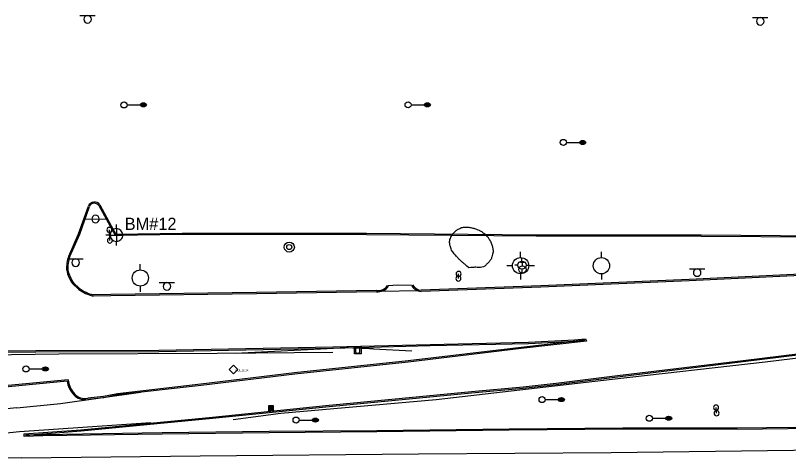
# Model space of a CAD drawing. Extents: x 2145380 to 2156929, y 139568 to 149130.
# Drawn here: x 2146530.1 to 2146909.9, y 143094.5 to 143313.3 of the extents above; entities that cross this region are included whole.
import ezdxf

# ---------------------------------------------------------------- set-up
doc = ezdxf.new("R2010")
doc.units = 0
for name, color, linetype in [('Default', 7, 'Continuous'), ('SURV_Benchmark', 7, 'Continuous'), ('SURV_Text', 7, 'Continuous'), ('TOPO_Asphalt', 7, 'Continuous'), ('TOPO_Curb Back', 7, 'Continuous'), ('TOPO_Guardrail', 7, 'Continuous'), ('TOPO_Light Pole', 7, 'Continuous'), ('TOPO_Misc', 7, 'Continuous'), ('TOPO_Power Pole', 7, 'Continuous'), ('TOPO_Power Pullbox', 7, 'Continuous'), ('TOPO_San Manhole', 7, 'Continuous'), ('TOPO_Sign', 7, 'Continuous'), ('TOPO_Tree Line', 7, 'Continuous'), ('TOPO_Water Fire Hydrant', 7, 'Continuous'), ('TOPO_Water Valve', 7, 'Continuous')]:
    doc.layers.add(name, color=color, linetype=linetype)

# ---------------------------------------------------------------- blocks, each defined once
blk = doc.blocks.new('LP')
at = {"layer": 'TOPO_Light Pole'}
blk.add_line((3.81, 0), (20.32, 0), dxfattribs=at)
for points in [[(20.32, 0), (27.94, 0)], [(20.32, 0), (23.5, 0)], [(20.83, 1.27), (27.43, 1.27)], [(20.83, 1.27), (23.5, 1.27)], [(23.71, 1.27), (27.43, 1.27)], [(23.71, 0), (27.94, 0)], [(20.83, -1.27), (27.43, -1.27)], [(20.83, -1.27), (23.5, -1.27)], [(23.71, -1.27), (27.43, -1.27)]]:
    blk.add_lwpolyline(points, dxfattribs=at)
blk.add_circle((0, 0), 3.81, dxfattribs=at)
blk.add_ellipse((24.13, 0), major_axis=(3.81, 0), ratio=0.666667, dxfattribs=at)
blk = doc.blocks.new('POST')
at = {"layer": 'TOPO_Misc'}
for start, end in [(89.99996, 180.00004), (179.99996, 270.00004), (359.99996, 90.00004), (269.99996, 0.00004)]:
    blk.add_arc((-0.01, 0.03), 3.16, start, end, dxfattribs=at)
blk = doc.blocks.new('FIRHYD')
at = {"layer": 'TOPO_Water Fire Hydrant'}
for p, q in [((-0.02, 10.16), (-0.03, 17.34)), ((10.16, 0.02), (17.34, 0.03)), ((-10.16, -0.02), (-17.34, -0.03)), ((0.02, -10.16), (0.03, -17.34))]:
    blk.add_line(p, q, dxfattribs=at)
blk.add_circle((0, 0), 10.16, dxfattribs=at)
blk = doc.blocks.new('CB')
at = {"layer": 'TOPO_Misc'}
for p, q in [((-3.08, 2.99), (3.24, 2.99)), ((-3.08, 2.68), (3.24, 2.68)), ((-3.08, 2.36), (3.24, 2.36)), ((-3.08, 2.05), (3.24, 2.05)), ((-3.08, 1.73), (3.24, 1.73)), ((-3.08, 1.4), (3.24, 1.4)), ((-3.08, 1.1), (3.24, 1.1)), ((-3.08, 0.77), (3.24, 0.77)), ((-3.08, 0.46), (3.24, 0.46)), ((-3.08, 0.14), (3.24, 0.14)), ((-3.08, -0.17), (3.24, -0.17)), ((-3.08, -0.48), (3.24, -0.48)), ((-3.08, -0.8), (3.24, -0.8)), ((-3.08, -1.11), (3.26, -1.11)), ((-3.08, -1.43), (3.26, -1.43)), ((-3.08, -1.75), (3.26, -1.75)), ((-3.08, -2.07), (3.26, -2.07)), ((-3.08, -2.39), (3.26, -2.39)), ((-3.08, -2.7), (3.26, -2.7)), ((-3.08, -3.02), (3.26, -3.02))]:
    blk.add_line(p, q, dxfattribs=at)
blk.add_lwpolyline([(3.26, -3.29), (3.24, 3.05), (-3.09, 3.04), (-3.08, -3.3), (3.26, -3.29)], dxfattribs=at)
blk = doc.blocks.new('POWPOL')
at = {"layer": 'TOPO_Power Pole'}
for p, q in [((0, 10.16), (0, 17.34)), ((0, -10.16), (0, -17.34))]:
    blk.add_line(p, q, dxfattribs=at)
blk.add_circle((0, 0), 10.16, dxfattribs=at)
blk = doc.blocks.new('pulbox')
at = {"layer": 'Default'}
blk.add_lwpolyline([(-5.38, -0.01), (-0.02, 5.42), (5.4, 0.06), (0.05, -5.36), (-5.38, -0.01)], dxfattribs=at)
blk.add_text('PULLBOX', height=2.54, dxfattribs=at).set_placement((2.54, -2.54))
blk = doc.blocks.new('WATVAL')
at = {"layer": 'Default'}
for p, q in [((-2.25, 9), (2.25, 9)), ((0, 4.5), (0, 9))]:
    blk.add_line(p, q, dxfattribs=at)
blk.add_circle((0, 0), 4.5, dxfattribs=at)
blk = doc.blocks.new('EXMHSS')
at = {"layer": 'Default'}
for radius in [6.3, 3.13]:
    blk.add_circle((0, 0), radius, dxfattribs=at)
blk = doc.blocks.new('BM')
at = {"layer": 'SURV_Benchmark'}
for p, q in [((0, 2.49), (0, 4.15)), ((-2.49, 0), (-4.16, 0)), ((4.16, 0), (2.49, 0)), ((0, -4.16), (0, -2.49))]:
    blk.add_line(p, q, dxfattribs=at)
for points in [[(-2.5, 0), (-2.49, 0), (0, 0), (0, -2.49), (0, -2.49)], [(-2.5, 0), (-2.49, 0), (0, 0), (0, -2.49), (0, -2.49)], [(0, 2.49), (0, 2.49), (0, 0), (2.49, 0), (2.49, 0), (2.49, 0)], [(0, 2.49), (0, 2.49), (0, 0), (2.49, 0), (2.49, 0), (2.49, 0), (2.49, 0)]]:
    blk.add_lwpolyline(points, dxfattribs=at)
for start, end in [(90.0638, 180.0068), (0.0638, 90.0068), (0.0638, 90.0068), (180.0638, 270.0068), (180.0638, 270.0068), (269.9472, 359.9927)]:
    blk.add_arc((0, 0), 2.5, start, end, dxfattribs=at)

msp = doc.modelspace()

# ---------------------------------------------------------------- linework, layer by layer
at = {"layer": 'TOPO_Asphalt'}
for p, q in [((2146576.46, 143202.65), (2146576.24, 143207.86)), ((2146727.7, 143177.96), (2146709.51, 143177.61))]:
    msp.add_line(p, q, dxfattribs=at)
for points in [[(2146712.97, 143180.61), (2146717.98, 143180.83), (2146724.61, 143180.64)], [(2146530.81, 143120.35), (2146552.18, 143122.58), (2146591.58, 143128.04)], [(2146530.81, 143120.35), (2146454.22, 143112.88)], [(2146596.66, 143112.95), (2146532, 143108.56), (2146508.54, 143106.19)], [(2146533.08, 143095.79), (2146446.58, 143095), (2146359.8, 143094.46), (2146423.36, 143099.13), (2146508.54, 143106.19)], [(2146533.08, 143095.79), (2146620.8, 143096.7), (2146728.01, 143097.79), (2146822.76, 143098.41), (2146912.25, 143099.54), (2147020.54, 143100.24), (2147131.17, 143101.32), (2147235.2, 143102.32), (2147277.67, 143102.76)]]:
    msp.add_lwpolyline(points, dxfattribs=at)
at = {"layer": 'TOPO_Curb Back'}
for points in [[(2146556.23, 143194.94), (2146561.06, 143205.93), (2146565.9, 143219.62)], [(2146556.79, 143194.71), (2146561.62, 143205.7), (2146566.46, 143219.39)], [(2146571.05, 143219.87), (2146576.58, 143209.64), (2146578.98, 143205.21), (2146612.05, 143205.72), (2146702.61, 143205.68), (2146785.83, 143204.89), (2146866.96, 143204.87), (2146925.47, 143204.4), (2146939.15, 143204.34), (2146943.78, 143207.95), (2146941.54, 143212.17)], [(2146571.55, 143220.19), (2146577.11, 143209.93), (2146579.34, 143205.82), (2146612.05, 143206.32), (2146702.61, 143206.28), (2146785.83, 143205.49), (2146866.96, 143205.47), (2146925.48, 143205), (2146938.94, 143204.94), (2146943.01, 143208.11), (2146941.09, 143211.74)], [(2146936.56, 143186.42), (2146861.15, 143182.86), (2146788.22, 143179.79), (2146729.35, 143177.64)], [(2146936.54, 143187.02), (2146861.12, 143183.46), (2146788.2, 143180.39), (2146729.36, 143178.24)], [(2146561.15, 143178.6), (2146558.1, 143181.44)], [(2146561.53, 143179.06), (2146558.56, 143181.83)], [(2146707.46, 143177.43), (2146648.5, 143176.48), (2146576.92, 143175.53), (2146568.17, 143175.36)], [(2146707.48, 143178.03), (2146648.49, 143177.08), (2146576.91, 143176.13), (2146568.24, 143175.96)], [(2145888.42, 143132.54), (2145934.97, 143136.29), (2145983.97, 143139.68), (2146045.76, 143137.81), (2146115.67, 143142.08), (2146170.97, 143145.46), (2146234.1, 143146.24), (2146328.36, 143147.21), (2146412.4, 143147.87), (2146464.49, 143148.31), (2146540.06, 143148.59), (2146600.53, 143148.76), (2146685.95, 143150.38), (2146733.76, 143151.59), (2146782.06, 143152.69), (2146804.67, 143153.83), (2146810.22, 143154.32), (2146810.59, 143153.13), (2146778.61, 143149.5), (2146723.01, 143142.86), (2146667.3, 143136.97), (2146621.29, 143131.42), (2146580.25, 143126.75), (2146573.42, 143125.34)], [(2145888.46, 143131.94), (2145935.02, 143135.69), (2145983.98, 143139.08), (2146045.76, 143137.21), (2146115.7, 143141.48), (2146170.99, 143144.86), (2146234.11, 143145.64), (2146328.36, 143146.61), (2146412.4, 143147.27), (2146464.49, 143147.71), (2146540.06, 143147.99), (2146600.54, 143148.16), (2146685.97, 143149.78), (2146733.77, 143150.99), (2146782.08, 143152.09), (2146804.71, 143153.23), (2146809.79, 143153.68), (2146809.8, 143153.64), (2146778.54, 143150.09), (2146722.94, 143143.46), (2146667.23, 143137.57), (2146621.22, 143132.02), (2146580.15, 143127.34), (2146573.3, 143125.93)], [(2146971.16, 143110.85), (2146884.74, 143109.79), (2146828.41, 143109.86), (2146772.57, 143109.36), (2146707.64, 143108.53), (2146654.7, 143108.12), (2146602.15, 143107.42), (2146543.46, 143106.54), (2146534.41, 143106.32), (2146534.33, 143107.54), (2146562.24, 143109.64), (2146626.86, 143115.86), (2146682.49, 143121.45), (2146754.14, 143128.38), (2146779.5, 143130.73), (2146795.72, 143132.53), (2146825.79, 143136.29), (2146887.61, 143143.7), (2146962.26, 143152.91)], [(2146971.15, 143111.44), (2146884.73, 143110.39), (2146828.41, 143110.46), (2146772.57, 143109.96), (2146707.63, 143109.13), (2146654.7, 143108.72), (2146602.14, 143108.02), (2146543.45, 143107.14), (2146534.97, 143106.93), (2146534.96, 143106.98), (2146562.29, 143109.04), (2146626.92, 143115.26), (2146682.55, 143120.86), (2146754.2, 143127.78), (2146779.56, 143130.13), (2146795.79, 143131.93), (2146825.86, 143135.69), (2146887.68, 143143.1), (2146962.33, 143152.31)], [(2146555.92, 143134.2), (2146526.51, 143131.33), (2146455.1, 143123.91), (2146431.26, 143121.71), (2146396.27, 143119.46), (2146350.09, 143117.2), (2146299.91, 143116.09), (2146246.29, 143114.58), (2146189.97, 143112.89), (2146131.43, 143111.03)], [(2146555.41, 143133.54), (2146526.57, 143130.74), (2146455.16, 143123.32), (2146431.31, 143121.11), (2146396.31, 143118.86), (2146350.11, 143116.6), (2146299.92, 143115.49), (2146246.31, 143113.98), (2146189.99, 143112.29), (2146131.45, 143110.43)], [(2146573.32, 143125.94), (2146565.55, 143125.11)], [(2146573.39, 143125.34), (2146565.64, 143124.52)]]:
    msp.add_lwpolyline(points, dxfattribs=at)
for centre, radius, start, end in [((2146568.89, 143218.27), 3.28, 35.8736, 155.7101), ((2146568.89, 143218.27), 2.68, 36.6665, 155.1999), ((2146571.29, 143189.22), 16.1, 159.2169, 184.0265), ((2146571.29, 143189.22), 15.5, 159.2728, 183.8644), ((2146573.83, 143192.18), 19.04, 192.4019, 214.3313), ((2146573.83, 143192.18), 18.44, 192.5386, 214.1261), ((2146572.65, 143194.28), 19.45, 233.753, 256.6902), ((2146572.65, 143194.28), 18.85, 233.8598, 256.4606), ((2146707.92, 143184.13), 6.71, 266.1076, 324.0825), ((2146707.92, 143184.13), 6.11, 265.8766, 324.0825), ((2146729.6, 143183.28), 5.65, 207.8693, 267.5079), ((2146729.6, 143183.28), 5.05, 207.8693, 267.2427), ((2146568.01, 143135.54), 12.76, 188.9783, 222.7059), ((2146568.01, 143135.54), 12.16, 186.3185, 222.7266), ((2146564.23, 143131.89), 7.51, 221.877, 280.814), ((2146564.23, 143131.89), 6.91, 221.8413, 281.0158)]:
    msp.add_arc(centre, radius, start, end, dxfattribs=at)
at = {"layer": 'TOPO_Guardrail'}
for points in [[(2147049.65, 143160.58), (2146984.46, 143153.27), (2146898.4, 143142.89), (2146823.2, 143134.27), (2146736.79, 143124.36), (2146660.39, 143117.58), (2146637.08, 143114.45)], [(2146551.37, 143146.86), (2146629.12, 143147.21), (2146686.04, 143147.75)], [(2146637.99, 143147.3), (2146689.63, 143149.87)], [(2146706.03, 143149.31), (2146724.88, 143148.43)], [(2146448.48, 143146.27), (2146516.32, 143146.42), (2146551.37, 143146.86)]]:
    msp.add_lwpolyline(points, dxfattribs=at)
msp.add_arc((2146685.9, 142804.41), 345.49, 86.6594, 89.3802, dxfattribs=at)
at = {"layer": 'TOPO_Misc'}
for p, q in [((2146697.21, 143150.16), (2146697.21, 143147.76)), ((2146699.29, 143147.76), (2146699.29, 143150.17))]:
    msp.add_line(p, q, dxfattribs=at)
msp.add_lwpolyline([(2146696.62, 143146.85), (2146696.62, 143150.61), (2146699.88, 143150.61), (2146699.88, 143146.85), (2146696.62, 143146.85)], dxfattribs=at)
msp.add_arc((2146698.25, 143148.58), 1.32, 218.3412, 322.0625, dxfattribs=at)
at = {"layer": 'TOPO_Sign'}
for points in [[(2146561.76, 143313.31), (2146569.26, 143313.32)], [(2146563.65, 143311.45), (2146563.65, 143311.45)], [(2146565.51, 143313.31), (2146565.51, 143313.31)], [(2146567.38, 143311.45), (2146567.38, 143311.45)], [(2146892.26, 143312.33), (2146899.75, 143312.34)], [(2146894.14, 143310.46), (2146894.14, 143310.46)], [(2146896.01, 143312.33), (2146896.01, 143312.33)], [(2146897.88, 143310.46), (2146897.88, 143310.46)], [(2146565.51, 143309.58), (2146565.51, 143309.58)], [(2146896.01, 143308.6), (2146896.01, 143308.6)], [(2146564.27, 143213.21), (2146575.15, 143213.27)], [(2146555.89, 143193.69), (2146563.38, 143193.7)], [(2146559.64, 143193.69), (2146559.64, 143193.69)], [(2146557.77, 143191.82), (2146557.77, 143191.82)], [(2146559.64, 143189.95), (2146559.64, 143189.95)], [(2146561.51, 143191.82), (2146561.51, 143191.82)], [(2146747.71, 143183.96), (2146747.78, 143186.22)], [(2146861.25, 143188.78), (2146868.74, 143188.78)], [(2146863.13, 143186.91), (2146863.13, 143186.91)], [(2146865, 143188.78), (2146865, 143188.78)], [(2146865, 143185.04), (2146865, 143185.04)], [(2146866.86, 143186.91), (2146866.86, 143186.91)], [(2146600.71, 143181.98), (2146608.2, 143181.99)], [(2146604.46, 143181.98), (2146604.46, 143181.98)], [(2146602.59, 143180.11), (2146602.59, 143180.11)], [(2146604.46, 143178.24), (2146604.46, 143178.24)], [(2146606.32, 143180.11), (2146606.32, 143180.11)], [(2146874.53, 143117.68), (2146874.31, 143120.48)]]:
    msp.add_lwpolyline(points, dxfattribs=at)
for centre, radius, start, end in [((2146565.51, 143311.45), 1.87, 90, 180), ((2146565.51, 143311.45), 1.87, 180, 270), ((2146565.51, 143311.45), 1.87, 360, 90), ((2146565.51, 143311.45), 1.87, 270, 0), ((2146896.01, 143310.46), 1.87, 90, 180), ((2146896.01, 143310.46), 1.87, 180, 270), ((2146896.01, 143310.46), 1.87, 360, 90), ((2146896.01, 143310.46), 1.87, 270, 0), ((2146569.41, 143213.23), 1.84, 47.4196, 227.4196), ((2146569.41, 143213.23), 1.84, 227.4196, 47.4196), ((2146559.64, 143191.82), 1.87, 90, 180), ((2146559.64, 143191.82), 1.87, 360, 90), ((2146559.64, 143191.82), 1.87, 180, 270), ((2146559.64, 143191.82), 1.87, 270, 0), ((2146865, 143186.91), 1.87, 90, 180), ((2146865, 143186.91), 1.87, 180, 270), ((2146865, 143186.91), 1.87, 360, 90), ((2146865, 143186.91), 1.87, 270, 0), ((2146604.46, 143180.11), 1.87, 90, 180), ((2146604.46, 143180.11), 1.87, 360, 90), ((2146604.46, 143180.11), 1.87, 180, 270), ((2146604.46, 143180.11), 1.87, 270, 0)]:
    msp.add_arc(centre, radius, start, end, dxfattribs=at)
at = {"layer": 'TOPO_Tree Line'}
msp.add_open_spline([(2146752.76, 143189.3), (2146753.6, 143189.35), (2146754.44, 143189.4), (2146755.28, 143189.45), (2146756.33, 143189.51), (2146757.38, 143189.38), (2146758.43, 143189.46), (2146760, 143189.56), (2146761.28, 143190.6), (2146762.46, 143191.91), (2146763.62, 143193.2), (2146764.18, 143194.55), (2146764.54, 143196.07), (2146764.75, 143196.93), (2146764.78, 143197.84), (2146764.59, 143198.68), (2146764.18, 143200.55), (2146763.52, 143202.31), (2146762.38, 143203.98), (2146761.75, 143204.9), (2146761.06, 143205.63), (2146760.18, 143206.26), (2146759.02, 143207.08), (2146757.86, 143207.71), (2146756.56, 143208.21), (2146755.67, 143208.55), (2146754.77, 143208.79), (2146753.85, 143208.98), (2146752.77, 143209.19), (2146751.66, 143209.29), (2146750.58, 143209.21), (2146749.7, 143209.14), (2146748.86, 143208.84), (2146748.02, 143208.42), (2146747.22, 143208.03), (2146746.57, 143207.57), (2146745.93, 143206.93), (2146744.92, 143205.93), (2146744.21, 143204.87), (2146743.73, 143203.57), (2146743.37, 143202.63), (2146743.34, 143201.59), (2146743.53, 143200.65), (2146743.75, 143199.56), (2146744.06, 143198.47), (2146744.68, 143197.47), (2146745.25, 143196.56), (2146745.84, 143195.76), (2146746.57, 143195.01), (2146747.62, 143193.92), (2146748.66, 143192.82), (2146749.8, 143191.84), (2146750.79, 143190.99), (2146751.77, 143190.15), (2146752.76, 143189.3), (2146752.76, 143189.3)], degree=3, dxfattribs=at)

# ---------------------------------------------------------------- block references
at = {"layer": 'SURV_Benchmark', "xscale": 1.25, "yscale": 1.25}
msp.add_blockref('BM', (2146579.7, 143205.36), dxfattribs=at)
at = {"layer": 'TOPO_Light Pole', "xscale": 0.39370000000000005, "yscale": 0.3937000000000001}
for p in [(2146583.41, 143269.35), (2146722.98, 143269.37), (2146799.25, 143250.86), (2146535.26, 143139.52), (2146788.82, 143124.44), (2146841.48, 143115.27), (2146667.93, 143114.34)]:
    msp.add_blockref('LP', p, dxfattribs=at)
at = {"layer": 'TOPO_Misc', "xscale": 0.39370000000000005, "yscale": 0.3937000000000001}
for name, p in [('POST', (2146576.24, 143207.86)), ('POST', (2146576.46, 143202.65)), ('POST', (2146747.71, 143183.96)), ('POST', (2146747.78, 143186.22)), ('CB', (2146655.62, 143120.12)), ('POST', (2146874.31, 143120.48)), ('POST', (2146874.53, 143117.68))]:
    msp.add_blockref(name, p, dxfattribs=at)
at = {"layer": 'TOPO_Power Pole', "xscale": 0.39370000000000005, "yscale": 0.3937000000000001}
for p in [(2146817.97, 143190.25), (2146591.42, 143184.23)]:
    msp.add_blockref('POWPOL', p, dxfattribs=at)
at = {"layer": 'TOPO_Power Pullbox', "xscale": 0.39370000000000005, "yscale": 0.3937000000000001}
msp.add_blockref('pulbox', (2146637.17, 143139.23), dxfattribs=at)
at = {"layer": 'TOPO_San Manhole', "xscale": 0.39370000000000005, "yscale": 0.3937000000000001}
msp.add_blockref('EXMHSS', (2146664.61, 143199.43), dxfattribs=at)
at = {"layer": 'TOPO_Water Fire Hydrant'}
for p, xscale, yscale in [((2146778.25, 143190.28), 0.39370000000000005, 0.3937000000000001), ((2146778.91, 143190.53), 0.19685000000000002, 0.19685000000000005)]:
    msp.add_blockref('FIRHYD', p, dxfattribs=dict(at, xscale=xscale, yscale=yscale))
at = {"layer": 'TOPO_Water Valve', "xscale": 0.39370000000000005, "yscale": 0.3937000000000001}
msp.add_blockref('WATVAL', (2146779.16, 143188.38), dxfattribs=at)

# ---------------------------------------------------------------- texts
at = {"layer": 'SURV_Text'}
msp.add_text('BM#12', height=6, dxfattribs=at).set_placement((2146583.75, 143207.85))

doc.saveas('drawing.dxf')
